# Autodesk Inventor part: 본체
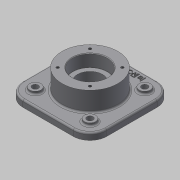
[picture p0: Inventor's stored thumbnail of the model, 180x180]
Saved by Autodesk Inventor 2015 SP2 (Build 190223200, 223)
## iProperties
Created: 2015-07
Part Number: 본체
Material: 일반
Document SubType Name: Modeling
Designer: AMC
Density: 1 g/cm^3
Appearance: 기본값
Mass: 540.471 g
Surface Area: 800.934 cm^2
Volume: 540.471 cm^3
Author: AMC
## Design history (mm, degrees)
sketch "스케치2"
  geometry: L1 (-75, 75)-(75, 75); L2 (75, 75)-(75, -75); L3 (75, -75)-(-75, -75); L4 (-75, -75)-(-75, 75); L5 (-75, 75)-(75, -75); L6 (75, 75)-(-75, -75); 1 further point
  constraints: 12 end point, 2 midpoint, 2 parallel, 1 horizontal, 1 perpendicular
  dimensions: "d2" = 150 distance of L2.end L3.end; "d3" = 150 distance of L1.end L2.end
extrude "돌출1" new body sketch "스케치2" distance "d4" = 12; taper "d5" = 0 deg
fillet "모깎기1" dims "d6" = 30
sketch "스케치3"
  geometry: C1 r 50 at (0, 0); 1 further point
  constraints: 1 centre point, 1 coincident
  dimensions: "d8" = 100 diameter of C1
sketch "스케치4"
  geometry: C1 r 50 at (0, 0); 1 further point
  constraints: 1 centre point, 1 coincident
  dimensions: "d9" = 100 diameter of C1
extrude "돌출2" join sketch "스케치4" distance "d10" = 23; taper "d11" = 0 deg
extrude "돌출3" join sketch "스케치3" distance "d12" = 35; taper "d13" = 0 deg
sketch "스케치5"
  geometry: L1 (49, 49)-(-49, 49); L2 (-49, 49)-(-49, -49); L3 (-49, -49)-(49, -49); L4 (49, -49)-(49, 49); L5 (49, 49)-(-49, -49); L6 (-49, 49)-(49, -49); C1 r 10 at (49, 49); C2 r 10 at (49, -49); C3 r 10 at (-49, 49); C4 r 10 at (-49, -49); 1 further point
  constraints: 12 end point, 4 centre point, 4 coincident, 2 midpoint, 2 parallel, 1 horizontal, 1 perpendicular
  dimensions: "d14" = 98 distance of L3.end L2.end; "d15" = 98 distance of L2.end L1.end; "d16" = 20 diameter of C1; "d17" = 20 diameter of C2; "d18" = 20 diameter of C3; "d19" = 20 diameter of C4
extrude "돌출4" join sketch "스케치5" distance "d20" = 5; taper "d21" = 0 deg
hole "구멍1" diameter "d24" = 45; stored, may be unused: countersink angle "d28" = 90 deg, drill point angle "d30" = 118 deg; dims "d22" = 10, "d23" = 10, "d25" = 6, "d26" = 62, "d27" = 22, "d29" = 8
hole "구멍2" diameter "d33" = 45; stored, may be unused: countersink angle "d37" = 90 deg, drill point angle "d39" = 118 deg; dims "d31" = 10, "d32" = 10, "d34" = 6, "d35" = 62, "d36" = 22, "d38" = 8
hole "구멍3" diameter "d42" = 11; stored, may be unused: countersink angle "d46" = 90 deg, drill point angle "d48" = 118 deg; dims "d40" = 10, "d41" = 10, "d43" = 6, "d44" = 62, "d45" = 22, "d47" = 8
hole "구멍4" diameter "d51" = 11; stored, may be unused: countersink angle "d55" = 90 deg, drill point angle "d57" = 118 deg; dims "d49" = 10, "d50" = 10, "d52" = 6, "d53" = 62, "d54" = 22, "d56" = 8
hole "구멍5" diameter "d60" = 11; stored, may be unused: countersink angle "d64" = 90 deg, drill point angle "d66" = 118 deg; dims "d58" = 10, "d59" = 10, "d61" = 6, "d62" = 62, "d63" = 22, "d65" = 8
hole "구멍6" diameter "d69" = 11; stored, may be unused: countersink angle "d73" = 90 deg, drill point angle "d75" = 118 deg; dims "d67" = 10, "d68" = 10, "d70" = 6, "d71" = 62, "d72" = 22, "d74" = 8
fillet "모깎기2" dims "d76" = 3
fillet "모깎기3" dims "d77" = 0.3
chamfer "모따기1" distance "d78" = 1; stored, may be unused: second distance "d79" = 2, angle "d80" = 45 deg
sketch "스케치6"
  geometry: L1 (-32.5, 67.991)-(33.866, 67.991); L2 (33.866, 67.991)-(33.866, 58.384); L3 (33.866, 58.384)-(-32.5, 58.384); L4 (-32.5, 58.384)-(-32.5, 67.991); 1 further point
  constraints: 2 other
feature "엠보싱1" sketch "스케치6" dims "d2" = 150, "d3" = 150, "d81" = 1, "d82" = 0
sketch "스케치7"
  geometry: L1 (0, 0)-(41, 0); L2 (0, 0)-(28.991, 28.991); A1 r 41 centre (0, 0) between (41, 0) and (28.991, 28.991); 1 further point
  constraints: 4 end point, 2 point on circle, 1 centre point, 1 coincident, 1 horizontal
  dimensions: "d83" = 82 diameter of A1; "d84" = 45 deg angle of L1 L2
hole "구멍7" sketch "스케치7" at (28.991, 28.991) diameter "d85" = 4.917; stored, may be unused: countersink angle "d89" = 90 deg, drill point angle "d91" = 118 deg; dims "d86" = 10, "d87" = 4, "d88" = 2, "d90" = 13
sketch "스케치8"
  geometry: L1 (0, 0)-(41, 0); L2 (0, 0)-(28.991, 28.991); A1 r 41 centre (0, 0) between (41, 0) and (28.991, 28.991); 1 further point
  constraints: 4 end point, 2 point on circle, 1 centre point, 1 coincident, 1 horizontal
  dimensions: "d95" = 82 diameter of A1; "d96" = 45 deg angle of L1 L2
hole "구멍8" sketch "스케치8" at (28.991, 28.991) diameter "d97" = 4.917; stored, may be unused: countersink angle "d101" = 90 deg, drill point angle "d103" = 118 deg; dims "d98" = 10, "d99" = 4, "d100" = 2, "d102" = 13
sketch "스케치9"
  geometry: 1 further point
node "솔리드1"
pattern_circular "원형 패턴1" dims angle "d93" = 360 deg
pattern_circular "원형 패턴2" dims angle "d105" = 360 deg
